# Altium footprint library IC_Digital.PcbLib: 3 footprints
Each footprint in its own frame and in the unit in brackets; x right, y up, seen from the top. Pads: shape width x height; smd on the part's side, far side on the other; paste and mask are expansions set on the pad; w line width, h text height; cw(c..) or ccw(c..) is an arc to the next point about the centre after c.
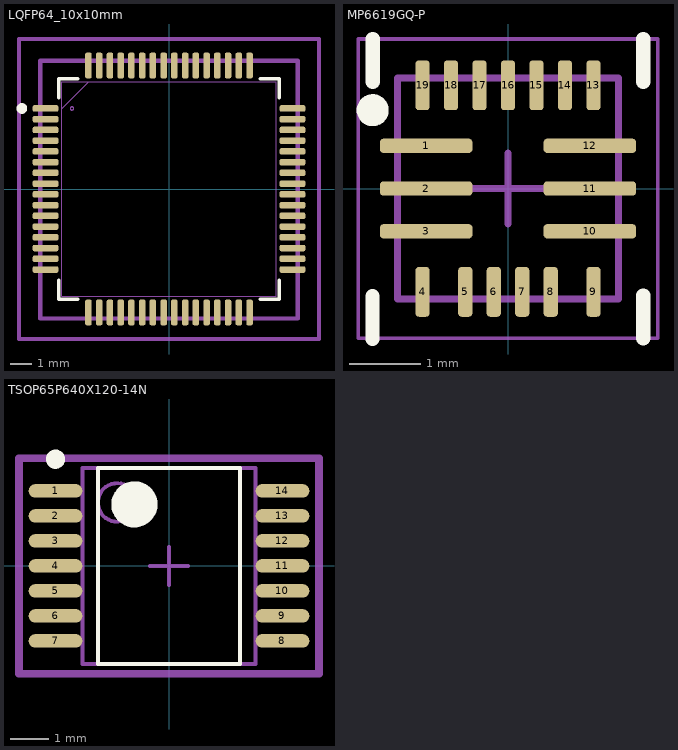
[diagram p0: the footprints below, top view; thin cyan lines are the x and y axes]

## LQFP64_10x10mm [mm] "10x10 mm"
height 1.6
pads (64):
  rrect50% 1.194x0.305 smd paste+0 mask+0.05: 1(-5.75,3.75) 2(-5.75,3.25) 3(-5.75,2.75) 4(-5.75,2.25) 5(-5.75,1.75) 6(-5.75,1.25) 7(-5.75,0.75) 8(-5.75,0.25) 9(-5.75,-0.25) 10(-5.75,-0.75) 11(-5.75,-1.25) 12(-5.75,-1.75) 13(-5.75,-2.25) 14(-5.75,-2.75) 15(-5.75,-3.25) 16(-5.75,-3.75) 33(5.75,-3.75) 34(5.75,-3.25) 35(5.75,-2.75) 36(5.75,-2.25) 37(5.75,-1.75) 38(5.75,-1.25) 39(5.75,-0.75) 40(5.75,-0.25) 41(5.75,0.25) 42(5.75,0.75) 43(5.75,1.25) 44(5.75,1.75) 45(5.75,2.25) 46(5.75,2.75) 47(5.75,3.25) 48(5.75,3.75)
  rrect50% 0.305x1.194 smd paste+0 mask+0.05: 17(-3.75,-5.75) 18(-3.25,-5.75) 19(-2.75,-5.75) 20(-2.25,-5.75) 21(-1.75,-5.75) 22(-1.25,-5.75) 23(-0.75,-5.75) 24(-0.25,-5.75) 25(0.25,-5.75) 26(0.75,-5.75) 27(1.25,-5.75) 28(1.75,-5.75) 29(2.25,-5.75) 30(2.75,-5.75) 31(3.25,-5.75) 32(3.75,-5.75) 49(3.75,5.75) 50(3.25,5.75) 51(2.75,5.75) 52(2.25,5.75) 53(1.75,5.75) 54(1.25,5.75) 55(0.75,5.75) 56(0.25,5.75) 57(-0.25,5.75) 58(-0.75,5.75) 59(-1.25,5.75) 60(-1.75,5.75) 61(-2.25,5.75) 62(-2.75,5.75) 63(-3.25,5.75) 64(-3.75,5.75)
Top Overlay:
  circle w0.3: c-6.851,3.75 r0.1
  lines w0.152: -5.131,-4.234 -5.131,-5.131 -4.234,-5.131 ; -5.131,4.234 -5.131,5.131 -4.234,5.131 ; 4.234,-5.131 5.131,-5.131 5.131,-4.234 ; 4.234,5.131 5.131,5.131 5.131,4.234
Mechanical 13:
  circle w0: c-4.518,3.75 r0.076
  lines w0.025: -5.004,3.734 -3.734,5.004 ; -5.004,-5.004 5.004,-5.004 5.004,5.004 -5.004,5.004 -5.004,-5.004
  lines w0.2: -6,-6.031 6,-6.031 6,5.969 -6,5.969 -6,-6.031
Component Courtyard:
  lines w0.2: -6.985,-6.985 -6.985,6.985 6.985,6.985 6.985,-6.985 -6.985,-6.985
3D body "LQFP64-10x10mm.step": height 1.6, standoff 0, extent -5.997,-5.997 5.997,5.997

## MP6619GQ-P [mm] "19-pin, QFN-19_3x3mm"
height 1
pads (19):
  rrect50% 1.3x0.2 smd: 1(-1.15,0.6) 2(-1.15,0) 3(-1.15,-0.6) 10(1.15,-0.6) 11(1.15,0) 12(1.15,0.6)
  rrect50% 0.2x0.7 smd: 4(-1.2,-1.45) 5(-0.6,-1.45) 6(-0.2,-1.45) 7(0.2,-1.45) 8(0.6,-1.45) 9(1.2,-1.45) 13(1.2,1.45) 14(0.8,1.45) 15(0.4,1.45) 16(0,1.45) 17(-0.4,1.45) 18(-0.8,1.45) 19(-1.2,1.45)
Top Overlay:
  circle w0.25: c-1.9,1.1 r0.1
  lines w0.2: -1.901,-2.112 -1.901,-1.512 ; -1.9,1.5 -1.9,2.1 ; 1.9,-2.1 1.9,-1.5 ; 1.9,1.5 1.9,2.1
Mechanical 13:
  lines w0.1: -1.55,-1.55 1.55,-1.55 1.55,1.55 -1.55,1.55 -1.55,-1.55
Component Courtyard:
  lines w0.05: -2.1,-2.1 2.1,-2.1 2.1,2.1 -2.1,2.1 -2.1,-2.1
  lines w0.1: -0.5,0 0.5,0 ; 0,-0.5 0,0.5
3D body "MP6619 (QFN-19, 3x3).step": height 0.92, standoff 0.02, extent -1.5,-1.5 1.5,1.5

## TSOP65P640X120-14N [mm] "TSOP, 14-Leads, Body 5.00x4.40mm, Pitch 0.65mm, IPC Medium Density"
height 1.2
pads (14):
  oval 1.4x0.35 smd mask+0.07: 1(-2.95,1.95) 2(-2.95,1.3) 3(-2.95,0.65) 4(-2.95,0) 5(-2.95,-0.65) 6(-2.95,-1.3) 7(-2.95,-1.95) 8(2.95,-1.95) 9(2.95,-1.3) 10(2.95,-0.65) 11(2.95,0) 12(2.95,0.65) 13(2.95,1.3) 14(2.95,1.95)
Top Overlay:
  circle w0.25: c-2.95,2.775 r0.125
  circle w0.6: c-0.9,1.6 r0.3
  lines w0.1: -1.85,-2.55 -1.85,2.55 1.85,2.55 1.85,-2.55 -1.85,-2.55
Mechanical 13:
  circle w0.1: c-1.35,1.65 r0.5
  lines w0.1: -2.25,-2.55 -2.25,2.55 2.25,2.55 2.25,-2.55 -2.25,-2.55
Component Courtyard:
  lines w0.1: -0.5,0 0.5,0 ; 0,-0.5 0,0.5
  lines w0.2: -3.9,-2.8 -3.9,2.8 3.9,2.8 3.9,-2.8 -3.9,-2.8
3D body "TSOP65P640X120-14N.step": height 1.2, standoff 0, extent -3.2,-2.55 3.2,2.55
